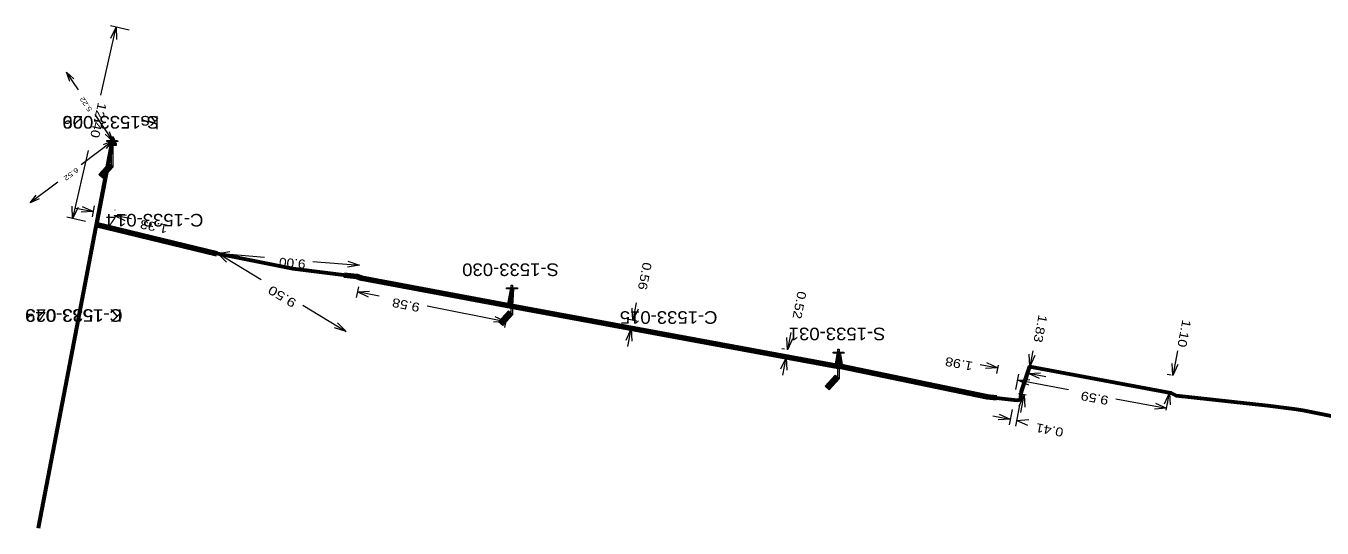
# Model space of a CAD drawing. Extents: x 600738 to 600908, y 1162430 to 1162522.
# Drawn here: x 600738.3 to 600820.3, y 1162490.6 to 1162522.3 of the extents above; entities that cross this region are included whole.
import ezdxf
from ezdxf.enums import TextEntityAlignment as Align

# ---------------------------------------------------------------- set-up
doc = ezdxf.new("R2010")
doc.units = 0
doc.header["$LTSCALE"] = 0.23
for name, color, linetype, lineweight in [('10', 7, 'Continuous', 13), ('11', 7, 'Continuous', 60), ('5', 7, 'Continuous', 13), ('6', 7, 'Continuous', 25), ('60', 7, 'Continuous', 13)]:
    doc.layers.add(name, color=color, linetype=linetype, lineweight=lineweight)

msp = doc.modelspace()

# ---------------------------------------------------------------- hatches: boundary and pattern name
at = {"layer": '10'}
for points in [[(600743.996, 1162514.778), (600743.996, 1162514.84), (600743.809, 1162515.278), (600743.683, 1162515.278), (600743.496, 1162514.84), (600743.496, 1162514.778)], [(600743.809, 1162515.153), (600743.809, 1162514.84), (600743.621, 1162514.84), (600743.621, 1162514.903), (600743.746, 1162514.903), (600743.746, 1162514.965), (600743.683, 1162514.965), (600743.683, 1162515.028), (600743.746, 1162515.028), (600743.746, 1162515.153)]]:
    msp.add_hatch(color=256, dxfattribs=at).paths.add_polyline_path(points)
at = {"layer": '5'}
for points in [[(600744.085, 1162515.008), (600743.385, 1162515.008), (600743.385, 1162515.071), (600744.078, 1162515.071)], [(600743.147, 1162512.691), (600742.888, 1162512.922), (600743.518, 1162513.622), (600743.784, 1162513.398)], [(600769.376, 1162505.686), (600768.676, 1162505.686), (600768.676, 1162505.749), (600769.369, 1162505.749)], [(600768.438, 1162503.369), (600768.179, 1162503.6), (600768.809, 1162504.3), (600769.075, 1162504.076)], [(600790.036, 1162501.626), (600789.336, 1162501.626), (600789.336, 1162501.689), (600790.029, 1162501.689)], [(600789.098, 1162499.309), (600788.839, 1162499.54), (600789.469, 1162500.24), (600789.735, 1162500.016)]]:
    msp.add_hatch(color=256, dxfattribs=at).paths.add_polyline_path(points)

# ---------------------------------------------------------------- linework, layer by layer
at = {"layer": '10'}
for points in [[(600743.996, 1162514.778), (600743.996, 1162514.84), (600743.809, 1162515.278), (600743.683, 1162515.278), (600743.496, 1162514.84), (600743.496, 1162514.778)], [(600743.809, 1162515.153), (600743.809, 1162514.84), (600743.621, 1162514.84), (600743.621, 1162514.903), (600743.746, 1162514.903), (600743.746, 1162514.965), (600743.683, 1162514.965), (600743.683, 1162515.028), (600743.746, 1162515.028), (600743.746, 1162515.153)]]:
    msp.add_lwpolyline(points, close=True, dxfattribs=at)
at = {"layer": '11', "lineweight": 90}
msp.add_line((600742.691, 1162509.758), (600750.348, 1162507.91), dxfattribs=at)
at = {"layer": '11'}
for points in [[(600739.08, 1162490.56), (600739.09, 1162490.67), (600740.877, 1162500.018), (600743.75, 1162515.05)], [(600743.75, 1162515.05), (600742.736, 1162509.787), (600750.41, 1162507.92), (600755.16, 1162506.98), (600759.2, 1162506.47), (600759.5, 1162506.37), (600768.835, 1162504.605), (600769.04, 1162505.7), (600768.981, 1162504.589), (600789.552, 1162500.804), (600789.7, 1162501.64), (600789.854, 1162500.77), (600799.08, 1162498.87), (600800.98, 1162498.65), (600801.2, 1162498.7), (600801.25, 1162499.2), (600801.78, 1162500.78), (600810.7, 1162499.11), (600811.04, 1162498.94), (600816.85, 1162498.32), (600818.51, 1162498.11), (600819.06, 1162498.01), (600833.12, 1162495.19)]]:
    msp.add_lwpolyline(points, dxfattribs=at)
at = {"layer": '11', "lineweight": 90}
msp.add_lwpolyline([(600758.4, 1162506.557), (600759.2, 1162506.47), (600759.5, 1162506.37), (600768.981, 1162504.589), (600789.552, 1162500.804), (600789.854, 1162500.77), (600799.08, 1162498.87), (600799.685, 1162498.801)], dxfattribs=at)
at = {"layer": '5'}
for points in [[(600744.085, 1162515.008), (600743.385, 1162515.008), (600743.385, 1162515.071), (600744.078, 1162515.071)], [(600743.77, 1162513.398), (600743.686, 1162513.405), (600743.686, 1162515.253), (600743.77, 1162515.246)], [(600743.147, 1162512.691), (600742.888, 1162512.922), (600743.518, 1162513.622), (600743.784, 1162513.398)], [(600769.376, 1162505.686), (600768.676, 1162505.686), (600768.676, 1162505.749), (600769.369, 1162505.749)], [(600769.061, 1162504.076), (600768.977, 1162504.083), (600768.977, 1162505.931), (600769.061, 1162505.924)], [(600768.438, 1162503.369), (600768.179, 1162503.6), (600768.809, 1162504.3), (600769.075, 1162504.076)], [(600790.036, 1162501.626), (600789.336, 1162501.626), (600789.336, 1162501.689), (600790.029, 1162501.689)], [(600789.721, 1162500.016), (600789.637, 1162500.023), (600789.637, 1162501.871), (600789.721, 1162501.864)], [(600789.098, 1162499.309), (600788.839, 1162499.54), (600789.469, 1162500.24), (600789.735, 1162500.016)]]:
    msp.add_lwpolyline(points, close=True, dxfattribs=at)
at = {"layer": '6'}
for points in [[(600739.08, 1162490.56), (600739.09, 1162490.67), (600740.877, 1162500.018), (600743.75, 1162515.05)], [(600743.75, 1162515.05), (600742.736, 1162509.787), (600750.41, 1162507.92), (600755.16, 1162506.98), (600759.2, 1162506.47), (600759.5, 1162506.37), (600768.835, 1162504.605), (600769.04, 1162505.7), (600768.981, 1162504.589), (600789.552, 1162500.804), (600789.7, 1162501.64), (600789.854, 1162500.77), (600799.08, 1162498.87), (600800.98, 1162498.65), (600801.2, 1162498.7), (600801.25, 1162499.2), (600801.78, 1162500.78), (600810.7, 1162499.11), (600811.04, 1162498.94), (600816.85, 1162498.32), (600818.51, 1162498.11), (600819.06, 1162498.01), (600833.12, 1162495.19)]]:
    msp.add_lwpolyline(points, dxfattribs=at)
at = {"layer": '60'}
for p, q in [((600743.006, 1162517.934), (600743.991, 1162522.232)), ((600744.814, 1162522.044), (600743.625, 1162522.316)), ((600741.594, 1162518.276), (600740.85, 1162519.39)), ((600742.633, 1162516.722), (600743.75, 1162515.05)), ((600741.764, 1162513.556), (600743.75, 1162515.05)), ((600742.206, 1162514.441), (600741.221, 1162510.142)), ((600740.286, 1162512.443), (600738.54, 1162511.13)), ((600741.439, 1162510.785), (600742.544, 1162510.575)), ((600742.48, 1162510.238), (600742.615, 1162510.943)), ((600743.921, 1162510.668), (600743.926, 1162510.693)), ((600742.044, 1162509.954), (600740.855, 1162510.226)), ((600744.961, 1162510.114), (600743.856, 1162510.325)), ((600753.154, 1162506.259), (600750.41, 1162507.92)), ((600753.359, 1162507.677), (600750.41, 1162507.92)), ((600756.431, 1162507.423), (600759.38, 1162507.18)), ((600759.311, 1162505.821), (600759.173, 1162505.136)), ((600760.626, 1162505.227), (600759.247, 1162505.504)), ((600755.796, 1162504.661), (600758.54, 1162503)), ((600763.659, 1162504.617), (600768.636, 1162503.616)), ((600768.761, 1162504.237), (600768.562, 1162503.249)), ((600776.888, 1162504.803), (600776.677, 1162503.698)), ((600776.929, 1162503.65), (600776.309, 1162503.769)), ((600776.362, 1162502.047), (600776.573, 1162503.152)), ((600776.93, 1162503.084), (600776.941, 1162503.082)), ((600786.667, 1162502.937), (600786.457, 1162501.832)), ((600786.263, 1162501.869), (600786.089, 1162501.902)), ((600801.968, 1162501.759), (600801.78, 1162500.78)), ((600811.134, 1162501.778), (600810.836, 1162500.205)), ((600786.151, 1162500.22), (600786.361, 1162501.325)), ((600786.72, 1162501.257), (600786.729, 1162501.255)), ((600798.648, 1162500.911), (600799.754, 1162500.702)), ((600799.786, 1162500.87), (600799.684, 1162500.334)), ((600801.412, 1162500.851), (600801.411, 1162500.851)), ((600800.905, 1162499.329), (600801.087, 1162500.289)), ((600801.711, 1162500.411), (600801.627, 1162499.968)), ((600802.802, 1162500.128), (600801.696, 1162500.336)), ((600810.73, 1162500.225), (600810.467, 1162500.274)), ((600804.227, 1162499.312), (600801.017, 1162499.921)), ((600810.332, 1162499.18), (600810.262, 1162499.193)), ((600810.421, 1162498.018), (600810.631, 1162499.123)), ((600801.13, 1162498.332), (600800.878, 1162497.004)), ((600801.545, 1162498.958), (600801.065, 1162499.05)), ((600801.22, 1162497.875), (600801.433, 1162498.979)), ((600807.233, 1162498.742), (600810.443, 1162498.133)), ((600810.491, 1162498.386), (600810.513, 1162498.501)), ((600799.443, 1162497.658), (600800.548, 1162497.449)), ((600800.665, 1162498.064), (600800.479, 1162497.08))]:
    msp.add_line(p, q, dxfattribs=at)
for points in [[(600743.641, 1162521.543), (600743.991, 1162522.232), (600744.006, 1162521.46)], [(600741.059, 1162518.808), (600740.85, 1162519.39), (600741.308, 1162518.974)], [(600743.541, 1162515.632), (600743.75, 1162515.05), (600743.292, 1162515.466)], [(600743.18, 1162514.809), (600743.75, 1162515.05), (600743.361, 1162514.569)], [(600739.11, 1162511.371), (600738.54, 1162511.13), (600738.929, 1162511.611)], [(600741.571, 1162510.832), (600741.221, 1162510.142), (600741.206, 1162510.915)], [(600741.843, 1162510.899), (600742.544, 1162510.575), (600741.772, 1162510.531)], [(600744.557, 1162510), (600743.856, 1162510.325), (600744.628, 1162510.368)], [(600751.142, 1162507.671), (600750.41, 1162507.92), (600751.173, 1162508.045)], [(600750.955, 1162507.371), (600750.41, 1162507.92), (600751.149, 1162507.692)], [(600758.648, 1162507.429), (600759.38, 1162507.18), (600758.617, 1162507.055)], [(600759.946, 1162505.172), (600759.247, 1162505.504), (600760.019, 1162505.54)], [(600777.002, 1162504.4), (600776.677, 1162503.698), (600776.634, 1162504.47)], [(600757.995, 1162503.549), (600758.54, 1162503), (600757.801, 1162503.228)], [(600767.938, 1162503.948), (600768.636, 1162503.616), (600767.864, 1162503.58)], [(600776.248, 1162502.45), (600776.573, 1162503.152), (600776.616, 1162502.38)], [(600786.781, 1162502.534), (600786.457, 1162501.832), (600786.413, 1162502.604)], [(600786.036, 1162500.624), (600786.361, 1162501.325), (600786.405, 1162500.554)], [(600799.052, 1162501.026), (600799.754, 1162500.702), (600798.982, 1162500.657)], [(600802.105, 1162501.481), (600801.78, 1162500.78), (600801.737, 1162501.552)], [(600811.159, 1162500.907), (600810.836, 1162500.205), (600810.791, 1162500.976)], [(600801.719, 1162499.597), (600801.017, 1162499.921), (600801.789, 1162499.965)], [(600802.399, 1162500.013), (600801.696, 1162500.336), (600802.468, 1162500.382)], [(600810.307, 1162498.421), (600810.631, 1162499.123), (600810.675, 1162498.351)], [(600801.107, 1162498.278), (600801.433, 1162498.979), (600801.475, 1162498.208)], [(600809.741, 1162498.457), (600810.443, 1162498.133), (600809.671, 1162498.088)], [(600799.847, 1162497.773), (600800.548, 1162497.449), (600799.777, 1162497.404)], [(600801.65, 1162497.049), (600800.948, 1162497.373), (600801.72, 1162497.417)]]:
    msp.add_lwpolyline(points, dxfattribs=at)

# ---------------------------------------------------------------- texts
at = {"layer": '10', "width": 1.1}
msp.add_text('ks1533-006', height=0.7955, rotation=180, dxfattribs=at).set_placement((600743.64, 1162516.623), align=Align.CENTER)
at = {"layer": '11', "width": 1.1}
for s, p in [('C-1533-014', (600746.414, 1162510.429)), ('C-1533-049', (600741.309, 1162504.4)), ('C-1533-015', (600778.936, 1162504.274))]:
    msp.add_text(s, height=0.7955, rotation=180, dxfattribs=at).set_placement(p, align=Align.CENTER)
at = {"layer": '5', "width": 1.1}
for s, p in [('S-1533-029', (600743.643, 1162516.617)), ('S-1533-030', (600768.934, 1162507.295)), ('S-1533-031', (600789.594, 1162503.235))]:
    msp.add_text(s, height=0.7955, rotation=180, dxfattribs=at).set_placement(p, align=Align.CENTER)
at = {"layer": '6', "width": 1.1}
msp.add_text('K-1533-023', height=0.7955, rotation=180, dxfattribs=at).set_placement((600741.309, 1162504.4), align=Align.CENTER)
at = {"layer": '60'}
for s, height, rotation, width, p in [('5.22', 0.3, 123.751, 1.3, (600742.473, 1162517.025)), ('12.40', 0.5625, 257.095, 1.2, (600742.842, 1162517.511)), ('6.52', 0.3, 216.958, 1.35, (600741.471, 1162513.379)), ('1.33', 0.5625, 169.208, 1.2, (600747.286, 1162509.737)), ('9.00', 0.5625, 175.284, 1.15, (600755.988, 1162507.526)), ('0.56', 0.5625, 259.185, 1.2, (600777.319, 1162507.407)), ('9.50', 0.5625, 148.819, 1.3, (600755.445, 1162504.949)), ('9.58', 0.5625, 168.635, 1.2, (600763.232, 1162504.769)), ('0.52', 0.5625, 259.233, 1.2, (600787.102, 1162505.577)), ('1.83', 0.5625, 259.102, 1.2, (600802.349, 1162504.084)), ('1.10', 0.5625, 259.276, 1.2, (600811.446, 1162503.779)), ('1.98', 0.5625, 169.327, 1.2, (600798.218, 1162501.059)), ('9.59', 0.5625, 169.257, 1.2, (600806.803, 1162498.89)), ('0.41', 0.5625, 169.257, 1.2, (600803.951, 1162496.87))]:
    msp.add_text(s, height=height, rotation=rotation, dxfattribs=dict(at, width=width)).set_placement(p)

doc.saveas('drawing.dxf')
